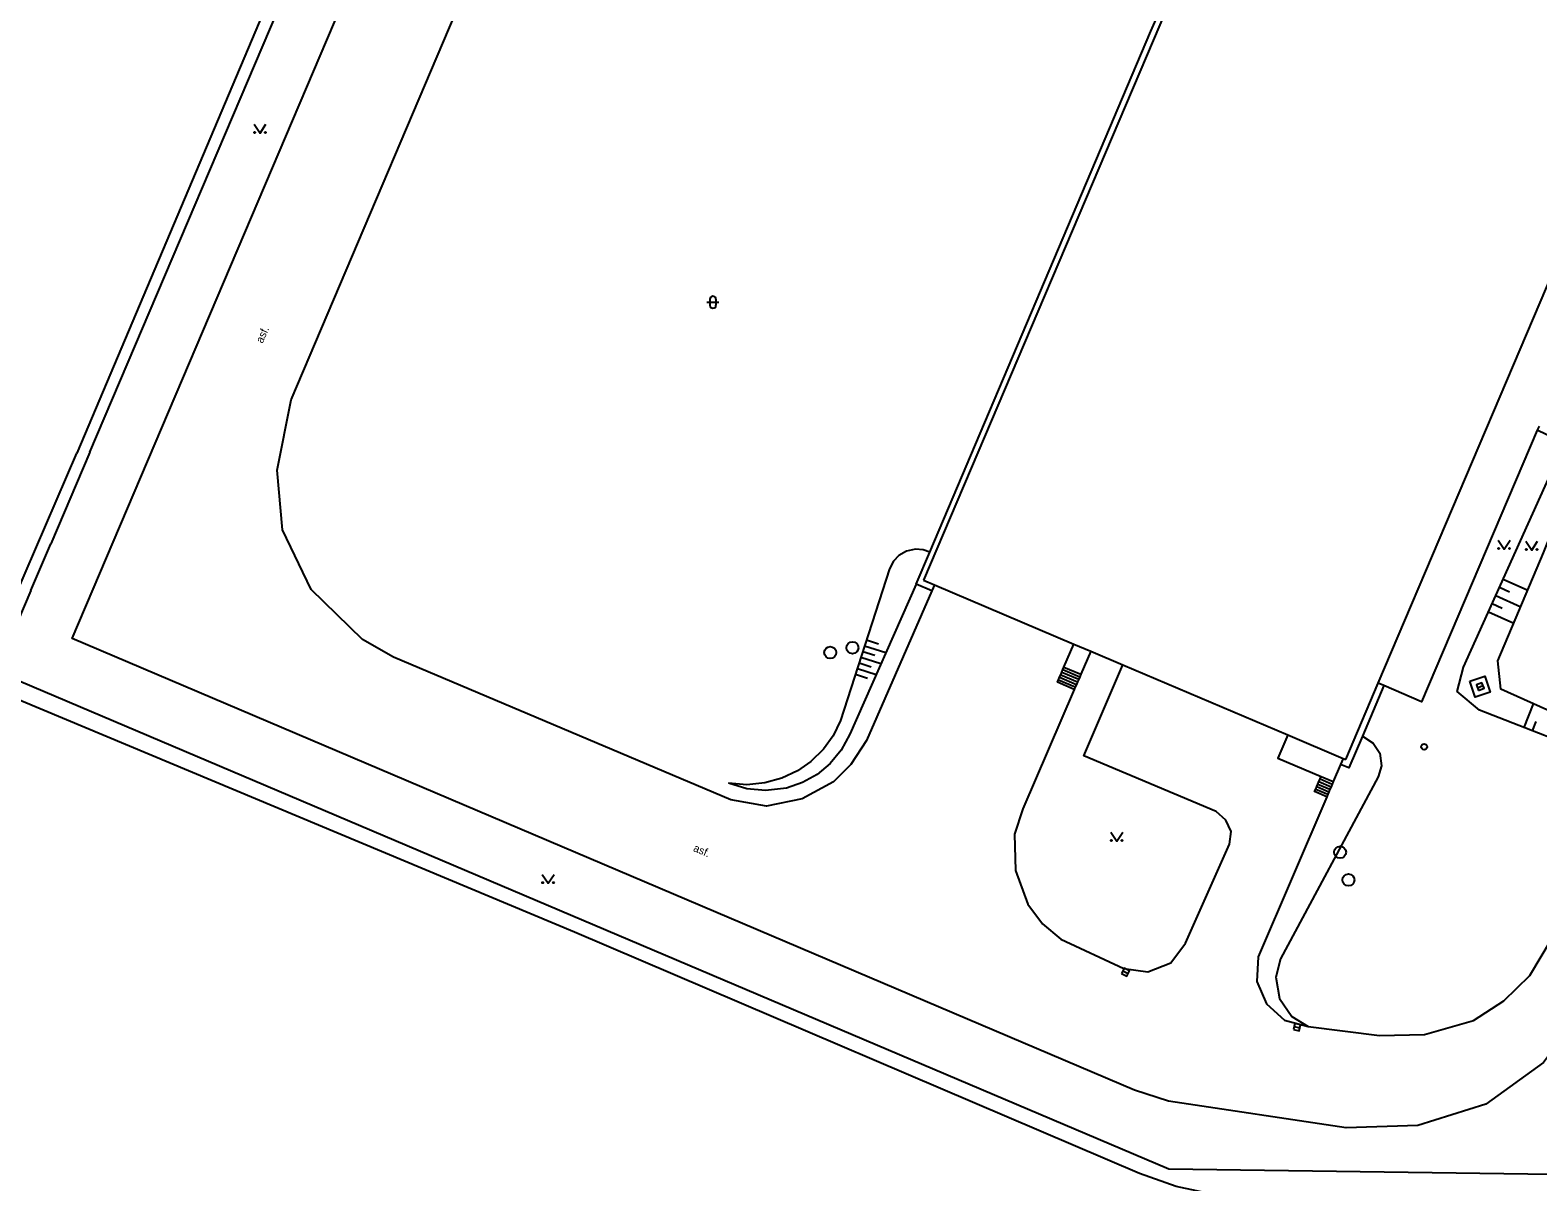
# Model space of a CAD drawing. Extents: x -596024 to -594475, y -1163820 to -1161957.
# Drawn here: x -595045 to -594919.3, y -1162691.2 to -1162595.2 of the extents above; entities that cross this region are included whole.
import ezdxf

# ---------------------------------------------------------------- set-up
doc = ezdxf.new("R2010")
doc.units = 0
for name, color, linetype in [('Level 10', 7, 'Continuous'), ('Level 11', 7, 'Continuous'), ('Level 14', 7, 'Continuous'), ('Level 15', 7, 'Continuous'), ('Level 23', 7, 'Continuous'), ('Level 27', 7, 'Continuous'), ('Level 28', 7, 'Continuous'), ('Level 36', 7, 'Continuous'), ('Level 40', 7, 'Continuous'), ('Level 5', 7, 'Continuous'), ('Level 7', 7, 'Continuous'), ('Level 8', 7, 'Continuous')]:
    doc.layers.add(name, color=color, linetype=linetype)

msp = doc.modelspace()

# ---------------------------------------------------------------- linework, layer by layer
at = {"layer": 'Level 10'}
for points in [[(-594846.75, -1162542.58), (-594847.02, -1162542.51), (-594848.96, -1162542.18), (-594851.99, -1162542.41), (-594854.86, -1162543.36), (-594857.46, -1162544.9), (-594859.6, -1162547.02), (-594861.11, -1162549.64), (-594913.9, -1162673.81), (-594915.2, -1162676.51), (-594918.78, -1162681.28), (-594923.61, -1162684.75), (-594929.28, -1162686.54), (-594935.26, -1162686.74), (-594950.08, -1162684.51), (-594952.91, -1162683.6), (-595041.5, -1162645.93), (-594955.82, -1162444.57), (-594948.99, -1162428.46), (-594885.06, -1162455.63)], [(-594969.8, -1162641.93), (-594975.27, -1162654.44), (-594976.57, -1162656.43), (-594978, -1162657.87), (-594980.63, -1162659.29), (-594983.61, -1162659.9), (-594986.57, -1162659.38), (-595014.7, -1162647.48), (-595017.3, -1162646.01), (-595021.58, -1162641.83), (-595023.95, -1162636.85), (-595024.42, -1162631.88), (-595023.23, -1162626.01), (-595006.47, -1162586.55), (-595005.42, -1162584.03)], [(-594919.16, -1162628.2), (-594919.31, -1162628.55)], [(-594919.31, -1162628.55), (-594928.97, -1162651.21), (-594932.11, -1162649.84)], [(-594938.43, -1162678.27), (-594932.46, -1162679.03), (-594928.71, -1162678.94), (-594924.63, -1162677.77), (-594922.09, -1162676.14), (-594919.94, -1162674.02), (-594918.14, -1162671.01), (-594903.7, -1162636.96)], [(-594969.59, -1162641.44), (-594969.8, -1162641.93)], [(-594956.56, -1162646.98), (-594957.38, -1162648.9)], [(-594957.93, -1162650.17), (-594962.21, -1162660.12), (-594962.9, -1162662.24), (-594962.82, -1162665.26), (-594961.8, -1162668.09), (-594960.59, -1162669.71), (-594959.05, -1162671.01), (-594953.79, -1162673.45), (-594951.78, -1162673.73), (-594949.87, -1162672.96), (-594948.65, -1162671.32), (-594944.98, -1162663.08), (-594944.85, -1162662.02), (-594945.28, -1162661.07), (-594946.08, -1162660.36), (-594957.14, -1162655.71), (-594953.87, -1162648.12)], [(-594957.65, -1162649.53), (-594957.75, -1162649.75)], [(-594957.56, -1162649.32), (-594957.65, -1162649.53)], [(-594957.47, -1162649.11), (-594957.56, -1162649.32)], [(-594957.38, -1162648.9), (-594957.47, -1162649.11)], [(-594957.84, -1162649.96), (-594957.93, -1162650.17)], [(-594957.75, -1162649.75), (-594957.84, -1162649.96)], [(-594932.11, -1162649.84), (-594932.57, -1162649.64)], [(-594935.72, -1162656.43), (-594936.33, -1162657.85)], [(-594935.5, -1162655.93), (-594935.72, -1162656.43)], [(-594936.51, -1162658.28), (-594936.6, -1162658.49)], [(-594936.42, -1162658.07), (-594936.51, -1162658.28)], [(-594936.33, -1162657.85), (-594936.42, -1162658.07)], [(-594936.87, -1162659.12), (-594942.58, -1162672.47), (-594942.71, -1162674.52), (-594941.9, -1162676.4), (-594940.39, -1162677.76), (-594938.43, -1162678.27)], [(-594936.78, -1162658.91), (-594936.87, -1162659.12)], [(-594936.69, -1162658.7), (-594936.78, -1162658.91)], [(-594936.6, -1162658.49), (-594936.69, -1162658.7)]]:
    msp.add_lwpolyline(points, dxfattribs=at)
at = {"layer": 'Level 11'}
for points in [[(-594963.95, -1162421.14), (-594960.5, -1162424.15), (-594958.64, -1162427.67), (-594958.13, -1162432.27), (-594958.84, -1162435.85), (-594980.2, -1162484.98), (-595000.54, -1162534.35), (-595020.69, -1162582.13), (-595041.12, -1162630.45)], [(-595040.04, -1162630.38), (-595018.08, -1162578.78)], [(-594951.53, -1162595.27), (-594950.08, -1162591.91)], [(-594969.98, -1162638.72), (-594951.53, -1162595.27)], [(-594916.32, -1162629.99), (-594919.31, -1162628.55)], [(-594971.11, -1162641.38), (-594969.98, -1162638.72)], [(-594969.8, -1162641.93), (-594971.11, -1162641.38)], [(-594958.79, -1162648.3), (-594957.97, -1162646.38)], [(-594958.88, -1162648.51), (-594958.79, -1162648.3)], [(-594958.79, -1162648.3), (-594957.38, -1162648.9)], [(-594957.93, -1162650.17), (-594959.33, -1162649.57), (-594959.24, -1162649.36)], [(-594959.24, -1162649.36), (-594959.15, -1162649.15)], [(-594959.24, -1162649.36), (-594957.84, -1162649.96)], [(-594959.15, -1162649.15), (-594959.06, -1162648.94)], [(-594959.15, -1162649.15), (-594957.75, -1162649.75)], [(-594959.06, -1162648.94), (-594958.97, -1162648.73)], [(-594959.06, -1162648.94), (-594957.65, -1162649.53)], [(-594958.97, -1162648.73), (-594958.88, -1162648.51)], [(-594958.97, -1162648.73), (-594957.56, -1162649.32)], [(-594958.88, -1162648.51), (-594957.47, -1162649.11)], [(-594924.95, -1162649.48), (-594923.7, -1162649.06), (-594923.25, -1162650.39), (-594924.5, -1162650.81), (-594924.95, -1162649.48)], [(-594932.11, -1162649.84), (-594933.9, -1162654.06)], [(-594940.12, -1162653.96), (-594940.94, -1162655.89), (-594937.34, -1162657.42)], [(-594933.9, -1162654.06), (-594935.03, -1162656.72), (-594935.72, -1162656.43)], [(-594937.79, -1162658.48), (-594937.7, -1162658.27)], [(-594937.7, -1162658.27), (-594937.61, -1162658.06)], [(-594937.7, -1162658.27), (-594936.69, -1162658.7)], [(-594937.61, -1162658.06), (-594937.52, -1162657.85)], [(-594937.61, -1162658.06), (-594936.6, -1162658.49)], [(-594937.52, -1162657.85), (-594937.43, -1162657.63)], [(-594937.52, -1162657.85), (-594936.51, -1162658.28)], [(-594937.43, -1162657.63), (-594937.34, -1162657.42)], [(-594937.43, -1162657.63), (-594936.42, -1162658.07)], [(-594937.34, -1162657.42), (-594936.33, -1162657.85)], [(-594936.87, -1162659.12), (-594937.88, -1162658.69), (-594937.79, -1162658.48)], [(-594937.79, -1162658.48), (-594936.78, -1162658.91)]]:
    msp.add_lwpolyline(points, dxfattribs=at)
at = {"layer": 'Level 14'}
for points in [[(-594915.13, -1162629.34), (-594914.63, -1162628.35), (-594913.82, -1162627.43), (-594912.85, -1162626.72), (-594911.79, -1162626.32), (-594906.82, -1162627.85), (-594905.59, -1162628.91), (-594904.86, -1162630.43), (-594904.7, -1162632.14), (-594905.16, -1162633.66), (-594908.86, -1162642.04), (-594909.03, -1162642.63), (-594913.87, -1162653.96), (-594922.34, -1162650.15), (-594922.59, -1162647.79), (-594918.78, -1162638.78), (-594915.39, -1162630.28)], [(-594904.93, -1162636.44), (-594905.74, -1162638.84), (-594913.15, -1162656.17), (-594924.13, -1162651.91), (-594925.99, -1162650.33), (-594925.46, -1162648.31), (-594921.74, -1162640.05), (-594918.01, -1162631.79), (-594916.32, -1162629.99)], [(-594969.98, -1162638.72), (-594970.53, -1162638.52), (-594971.17, -1162638.46), (-594971.91, -1162638.62), (-594972.55, -1162638.99), (-594973.01, -1162639.48), (-594973.33, -1162640.12), (-594977.42, -1162652.76), (-594978.05, -1162654.05), (-594978.85, -1162655.15), (-594979.9, -1162656.19), (-594981.02, -1162656.96), (-594982.33, -1162657.58), (-594983.73, -1162657.97), (-594985.24, -1162658.12), (-594986.76, -1162657.99)], [(-594971.11, -1162641.38), (-594976.66, -1162653.91), (-594977.38, -1162655.23), (-594978.3, -1162656.35), (-594979.38, -1162657.25), (-594980.6, -1162657.93), (-594981.94, -1162658.39), (-594983.68, -1162658.6), (-594985.23, -1162658.46), (-594986.76, -1162657.99)], [(-594933.9, -1162654.06), (-594932.99, -1162654.64), (-594932.45, -1162655.49), (-594932.31, -1162656.53), (-594932.58, -1162657.45), (-594940.72, -1162672.64), (-594941.12, -1162674.16), (-594940.82, -1162675.96), (-594939.77, -1162677.45), (-594938.43, -1162678.27)]]:
    msp.add_lwpolyline(points, dxfattribs=at)
at = {"layer": 'Level 15'}
for points in [[(-594922.45, -1162641.64), (-594921.63, -1162642.02)], [(-594922.15, -1162640.96), (-594920.09, -1162641.89)], [(-594923.07, -1162643.01), (-594922.23, -1162643.39)], [(-594922.76, -1162642.33), (-594920.68, -1162643.27)], [(-594923.38, -1162643.69), (-594921.26, -1162644.65)], [(-594974.55, -1162647.35), (-594975.56, -1162647.02)], [(-594973.65, -1162647.12), (-594975.41, -1162646.55)], [(-594974.25, -1162646.4), (-594975.26, -1162646.07)], [(-594974.86, -1162648.3), (-594975.87, -1162647.98)], [(-594974.06, -1162648.04), (-594975.72, -1162647.5)], [(-594975.17, -1162649.25), (-594976.18, -1162648.93)], [(-594974.46, -1162648.96), (-594976.02, -1162648.45)], [(-594919.66, -1162651.36), (-594920.43, -1162653.35)], [(-594919.43, -1162652.84), (-594919.73, -1162653.62)]]:
    msp.add_lwpolyline(points, dxfattribs=at)
at = {"layer": 'Level 23'}
msp.add_lwpolyline([(-594920.16, -1162797.38), (-594923.43, -1162784.55), (-594926.64, -1162775.9), (-594936.32, -1162762.45), (-594941.69, -1162753.93), (-594942.67, -1162750.76), (-594942.68, -1162746.07), (-594933.74, -1162698.76), (-594934.07, -1162695.98), (-594936.51, -1162694.37), (-594949.43, -1162691.63), (-594952.5, -1162690.54), (-594999.6, -1162670.42), (-595047.6, -1162650.36), (-595048.79, -1162649.56), (-595048.89, -1162648.47), (-595041.12, -1162630.45)], dxfattribs=at)
at = {"layer": 'Level 27'}
for p, q in [((-594924.3, -1162650.02), (-594923.84, -1162649.84)), ((-594953.89, -1162673.65), (-594953.43, -1162673.85)), ((-594939.59, -1162678.28), (-594939.11, -1162678.38))]:
    msp.add_line(p, q, dxfattribs=at)
for points in [[(-594924.21, -1162650.25), (-594923.75, -1162650.07), (-594923.93, -1162649.61), (-594924.39, -1162649.79)], [(-594953.99, -1162673.87), (-594953.54, -1162674.08), (-594953.33, -1162673.63), (-594953.78, -1162673.42)], [(-594939.65, -1162678.52), (-594939.16, -1162678.63), (-594939.05, -1162678.14), (-594939.54, -1162678.03)]]:
    msp.add_lwpolyline(points, close=True, dxfattribs=at)
for centre in [(-594978.28, -1162647.09), (-594976.43, -1162646.69), (-594935.76, -1162663.75), (-594935.06, -1162666.06)]:
    msp.add_circle(centre, 0.5, dxfattribs=at)
at = {"layer": 'Level 28'}
msp.add_circle((-594928.75, -1162654.95), 0.25, dxfattribs=at)
at = {"layer": 'Level 36'}
for p, q in [((-594988.56, -1162617.87), (-594987.56, -1162617.87)), ((-594988.31, -1162617.62), (-594988.31, -1162618.12)), ((-594987.81, -1162617.62), (-594987.81, -1162618.12))]:
    msp.add_line(p, q, dxfattribs=at)
for points in [[(-595026.34, -1162603.01), (-595025.84, -1162603.76), (-595025.34, -1162603.01)], [(-594922.58, -1162637.71), (-594922.08, -1162638.46), (-594921.58, -1162637.71)], [(-594920.28, -1162637.8), (-594919.78, -1162638.55), (-594919.28, -1162637.8)], [(-594954.89, -1162662.07), (-594954.39, -1162662.82), (-594953.89, -1162662.07)], [(-595002.31, -1162665.59), (-595001.81, -1162666.34), (-595001.31, -1162665.59)]]:
    msp.add_lwpolyline(points, dxfattribs=at)
for centre in [(-595026.29, -1162603.71), (-595025.39, -1162603.71), (-594922.53, -1162638.41), (-594921.63, -1162638.41), (-594920.23, -1162638.5), (-594919.33, -1162638.5), (-594954.84, -1162662.77), (-594953.94, -1162662.77), (-595002.26, -1162666.29), (-595001.36, -1162666.29)]:
    msp.add_circle(centre, 0.05, dxfattribs=at)
for centre, start, end in [((-594988.06, -1162617.62), 0, 180), ((-594988.06, -1162618.12), 180, 0)]:
    msp.add_arc(centre, 0.25, start, end, dxfattribs=at)
at = {"layer": 'Level 5'}
for points in [[(-594932.57, -1162649.64), (-594907.79, -1162591.35), (-594907.59, -1162590.88), (-594902.28, -1162578.39)], [(-594949.68, -1162592.09), (-594970.49, -1162641.06)], [(-594970.49, -1162641.06), (-594969.59, -1162641.44)], [(-594969.59, -1162641.44), (-594957.97, -1162646.38)], [(-594957.97, -1162646.38), (-594956.56, -1162646.98)], [(-594956.56, -1162646.98), (-594953.87, -1162648.12)], [(-594953.87, -1162648.12), (-594940.12, -1162653.96)], [(-594935.28, -1162656.02), (-594932.57, -1162649.64)], [(-594940.12, -1162653.96), (-594935.5, -1162655.93)], [(-594935.5, -1162655.93), (-594935.28, -1162656.02)]]:
    msp.add_lwpolyline(points, dxfattribs=at)
at = {"layer": 'Level 7'}
for points in [[(-595040.04, -1162630.38), (-595043.29, -1162638.01)], [(-595044.95, -1162641.91), (-595047.84, -1162648.63), (-594950.04, -1162690.15), (-594900.15, -1162690.86)]]:
    msp.add_lwpolyline(points, dxfattribs=at)
at = {"layer": 'Level 8'}
msp.add_lwpolyline([(-595044.95, -1162641.91), (-595043.29, -1162638.01)], dxfattribs=at)

# ---------------------------------------------------------------- texts
at = {"layer": 'Level 40'}
for rotation, p in [(66.12, (-595025.63, -1162621.34)), (336.97, (-594989.76, -1162663.63))]:
    msp.add_text('asf.', height=0.65, rotation=rotation, dxfattribs=at).set_placement(p)

doc.saveas('drawing.dxf')
